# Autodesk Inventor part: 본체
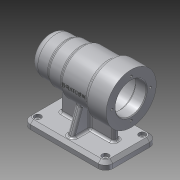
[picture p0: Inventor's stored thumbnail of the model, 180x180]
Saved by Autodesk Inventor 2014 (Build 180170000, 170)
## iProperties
Created: 2016-06
Part Number: 본체
Material: 알루미늄 6061
Document SubType Name: Modeling
Designer: USER
Density: 2.71 g/cm^3
Appearance: 알루미늄 - 평지
Author: USER
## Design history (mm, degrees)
sketch "스케치1"
  geometry: L1 (-56, 0)-(56, 0); L2 (-56, 0)-(-56, 25); L3 (-56, 25)-(-31, 25); L4 (-31, 25)-(-31, 27); L5 (-31, 27)-(-11, 27); L6 (-11, 27)-(-11, 30); L7 (-11, 30)-(28, 30); L8 (28, 30)-(28, 34); L9 (28, 34)-(56, 34); L10 (-50, 0)-(-50, 10.5); L11 (-50, 10.5)-(-47, 10.5); L12 (-47, 10.5)-(-47, 16); L13 (-47, 16)-(-43, 16); L14 (-43, 16)-(-43, 17.5); L15 (-43, 17.5)-(-25, 17.5); L16 (-25, 17.5)-(-25, 21); L17 (-25, 21)-(-13, 21); L18 (-13, 21)-(-13, 24); L19 (-13, 24)-(41, 24); L20 (41, 24)-(41, 21); L21 (41, 21)-(56, 21); L22 (56, 21)-(56, 34); 2 further points
  constraints: 44 end point, 15 parallel, 6 perpendicular, 1 coincident, 1 horizontal, 1 midpoint, 1 point on line
  dimensions: "d0" = 112 distance of L1.start L1.end; "d2" = 25 distance of L2.end L3.end; "d4" = 50 diameter of L3 L1; "d5" = 54 diameter of L5 L1; "d6" = 60 diameter of L7 L1; "d7" = 68 diameter of L9 L1; "d8" = 45 distance between parallel lines of L6 L2; "d9" = 84 distance between parallel lines of L8 L2; "d10" = 3 distance between parallel lines of L12 L10; "d11" = 4 distance between parallel lines of L14 L12; "d12" = 18 distance between parallel lines of L16 L14; "d13" = 12 distance between parallel lines of L18 L16; "d14" = 54 distance between parallel lines of L20 L18; "d15" = 15 distance between parallel lines of L22 L20; "d16" = 112 distance between parallel lines of L2 L22; "d17" = 21 diameter of L11 L1; "d18" = 32 diameter of L13 L1; "d19" = 35 diameter of L15 L1; "d20" = 42 diameter of L17 L1; "d21" = 48 diameter of L19 L1; "d22" = 42 diameter of L21 L1
revolve "회전1" sketch "스케치1" stored, may be unused: angle "d23" = 90 deg
node "작업 평면1"
sketch "스케치2"
  geometry: L1 (-56, -35)-(56, -35); L2 (56, -35)-(56, 35); L3 (56, 35)-(-56, 35); L4 (-56, 35)-(-56, -35); L5 (-56, -35)-(56, 35); L6 (56, -35)-(-56, 35); 1 further point
  constraints: 12 end point, 2 midpoint, 2 parallel, 1 horizontal, 1 perpendicular
  dimensions: "d25" = 112 distance of L3.end L2.end; "d26" = 70 distance of L2.end L1.end
extrude "돌출1" join sketch "스케치2" distance "d27" = 10; taper "d28" = 0 deg
sketch "스케치3"
  geometry: L1 (56, 35)-(-56, 35) reference; L2 (-56, 35)-(-56, -35) reference; L3 (-4, -28)-(4, -28); L4 (4, -28)-(4, 28); L5 (4, 28)-(-4, 28); L6 (-4, 28)-(-4, -28); L7 (-4, -28)-(4, 28); L8 (4, -28)-(-4, 28); L9 (-36, -4)-(36, -4); L10 (36, -4)-(36, 4); L11 (36, 4)-(-36, 4); L12 (-36, 4)-(-36, -4); L13 (-36, -4)-(36, 4); L14 (36, -4)-(-36, 4); 1 further point
  constraints: 24 end point, 4 midpoint, 4 parallel, 2 horizontal, 2 perpendicular
  dimensions: "d29" = 8 distance of L5.end L4.end; "d30" = 7 distance between parallel lines of L1 L5; "d31" = 8 distance of L10.end L9.end; "d32" = 20 distance between parallel lines of L2 L12
extrude "돌출2" join sketch "스케치3" stored distance "d33" = 10; taper "d34" = 0 deg
feature "면 기울기1" dims angle "d35" = 20 deg
feature "면 기울기2" dims angle "d36" = 20 deg
sketch "스케치4"
  geometry: C1 r 34 at (0, 0) reference; 1 further point
  constraints: 1 vertical alignment
  dimensions: "d37" = 26 distance of point (0, 26) C1.centre
hole "구멍1" sketch "스케치4" at (0, 26) diameter "d38" = 3.242; stored, may be unused: countersink angle "d42" = 90 deg, drill point angle "d44" = 118 deg; dims "d39" = 8, "d40" = 4, "d41" = 2, "d43" = 11
sketch "스케치5"
  geometry: L1 (-46, -25)-(46, -25); L2 (46, -25)-(46, 25); L3 (46, 25)-(-46, 25); L4 (-46, 25)-(-46, -25); L5 (-46, -25)-(46, 25); L6 (46, -25)-(-46, 25); 5 further points
  constraints: 12 end point, 4 coincident, 2 midpoint, 2 parallel, 1 horizontal, 1 perpendicular
  dimensions: "d48" = 92 distance of L3.end L2.end; "d49" = 50 distance of L2.end L1.end
hole "구멍2" sketch "스케치5" at (-46, 25), (-46, -25), (46, -25), (46, 25) diameter "d50" = 5; stored, may be unused: countersink angle "d54" = 90 deg, drill point angle "d56" = 118 deg; dims "d51" = 8, "d52" = 9, "d53" = 4, "d55" = 11
fillet "모깎기1" dims "d57" = 3
fillet "모깎기2" dims "d58" = 0.3
chamfer "모따기1" distance "d59" = 1; stored, may be unused: second distance "d60" = 2, angle "d61" = 45 deg
fillet "모깎기3" dims "d62" = 10
chamfer "모따기2" distance "d63" = 4; stored, may be unused: second distance "d64" = 2, angle "d65" = 45 deg
fillet "모깎기4" dims "d66" = 3
fillet "모깎기5" dims "d67" = 3, "d68" = 3
fillet "모깎기6" dims "d69" = 3
fillet "모깎기7" dims "d70" = 3
node "작업 평면4"
sketch "스케치7"
  geometry: L1 (102, 36)-(102, 104) reference; 2 further points
  constraints: 1 horizontal alignment, 1 other
  dimensions: "d74" = 48 distance from line of L1 point (54, 70)
feature "엠보싱1" sketch "스케치7" dims "d0" = 112, "d2" = 25, "d4" = 50, "d5" = 54, "d6" = 60, "d7" = 68, "d8" = 45, "d9" = 84, "d10" = 3, "d11" = 4, "d12" = 18, "d13" = 12, "d14" = 54, "d15" = 15, "d16" = 112, "d17" = 21, "d18" = 32, "d19" = 35, "d20" = 42, "d21" = 48, "d22" = 42, "d75" = 0.5, "d76" = 0
node "솔리드1"
pattern_circular "원형 패턴1" dims angle "d46" = 360 deg
